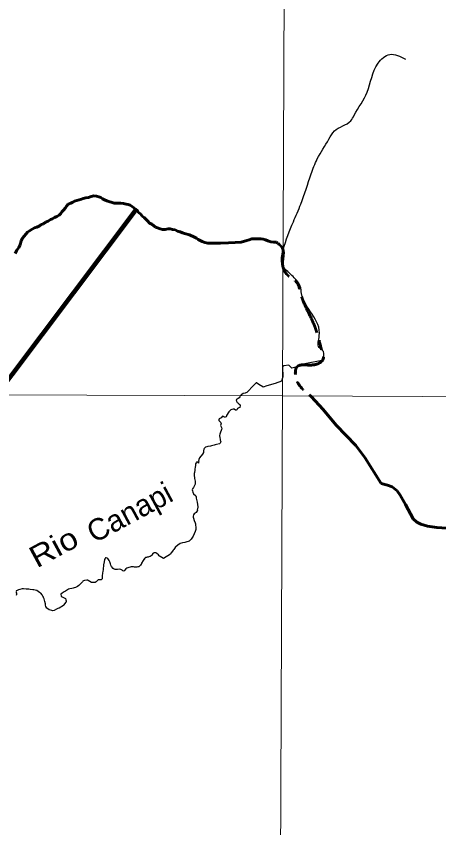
# Model space of a CAD drawing. Extents: x 553962 to 842807, y 8883888 to 9032388.
# Drawn here: x 658730 to 668504, y 8994810 to 9013599 of the extents above; entities that cross this region are included whole.
import ezdxf
from ezdxf.enums import TextEntityAlignment as Align

# ---------------------------------------------------------------- set-up
doc = ezdxf.new("R2010")
doc.units = 0
doc.header["$LTSCALE"] = 150
doc.linetypes.add('LONG_DASH_SHORT_DASH', pattern=[9.9, 6, -1.2, 1.5, -1.2])
for name, color, linetype, lineweight in [('1', 7, 'Continuous', 13), ('24', 7, 'Continuous', 25), ('7', 7, 'LONG_DASH_SHORT_DASH', 60), ('9', 7, 'Continuous', 90)]:
    doc.layers.add(name, color=color, linetype=linetype, lineweight=lineweight)
doc.layers.add('49', color=7, linetype='Continuous')

msp = doc.modelspace()

# ---------------------------------------------------------------- linework, layer by layer
at = {"layer": '1'}
for points in [[(664968.2, 9023436.8), (664657.1, 8949509), (664397.1, 8890880.2)], [(565303.2, 9005146.6), (664889.8, 9004806.7), (719872.1, 9004543.9), (790635.8, 9004109)]]:
    msp.add_lwpolyline(points, dxfattribs=at)
at = {"layer": '24'}
for points in [[(664888.7, 9005478.8), (664900.1, 9005251.2), (664869.8, 9005153.3), (664865.4, 9005145.8), (664717.4, 9005095.4), (664528.5, 9005045), (664441.2, 9005012.7), (664432.8, 9005015.5), (664343.5, 9005072.6), (664286.2, 9005107.2), (664280.8, 9005109), (664271.5, 9005101.5), (664208.7, 9005038.3), (664080.1, 9004905.7)], [(665798.1, 9005626.6), (665405.1, 9005550.8), (665165.6, 9005466.5), (665101.5, 9005450.6), (665032.2, 9005519.9), (664921.3, 9005506.1), (664888.7, 9005478.8)], [(664080.1, 9004905.7), (664063.5, 9004888.7), (664040.8, 9004876.6), (664021.9, 9004870), (663980.2, 9004861.2), (663946.3, 9004843.8), (663931.6, 9004832.2), (663929.7, 9004827.5), (663925.3, 9004825.6), (663922.8, 9004820.1), (663917.9, 9004815.5), (663910.5, 9004801.1), (663899, 9004783.8), (663883.9, 9004765), (663863.8, 9004751.9), (663845.5, 9004742.3), (663830.7, 9004729.4), (663824.8, 9004721.3), (663819.7, 9004702.6), (663823.3, 9004691.5), (663824.1, 9004683.3), (663832.8, 9004668.7), (663842.4, 9004656.8), (663854.1, 9004648.1), (663869.6, 9004633.8), (663887.6, 9004620.7), (663907, 9004598.9), (663907, 9004598.9), (663910.9, 9004584.5), (663902.4, 9004543.4), (663900.7, 9004539.3), (663881.2, 9004529), (663848.8, 9004520.2), (663839.5, 9004493.6), (663833.8, 9004483.1), (663820.7, 9004477), (663803.2, 9004478.8), (663774.4, 9004497.4), (663769.2, 9004499), (663746.7, 9004499.8), (663720.6, 9004496.7), (663695.8, 9004484.7), (663668.4, 9004461.3), (663648.1, 9004440.9), (663597.4, 9004352.2)], [(663597.4, 9004352.2), (663591.9, 9004338.7), (663585.2, 9004327.5), (663562, 9004318.3), (663545.8, 9004318.1), (663534.7, 9004324.6), (663525, 9004333.9), (663497.8, 9004335.9), (663473.3, 9004304.2), (663451.5, 9004291.8), (663425.3, 9004274.1), (663419.2, 9004251.7), (663419.6, 9004240.3), (663428.8, 9004227), (663461.2, 9004195.3), (663463.7, 9004190.3), (663466.9, 9004175.9), (663457.9, 9004121.1), (663483.9, 9004058.1), (663479.5, 9004030.4), (663444.7, 9003947.7), (663436.1, 9003919.8), (663430, 9003892.9), (663436.2, 9003836.4), (663444.6, 9003808.5), (663450.1, 9003780.8), (663459.3, 9003752.9), (663454.4, 9003726), (663450.1, 9003716.1), (663431.3, 9003702.2), (663360.9, 9003681.5), (663332.3, 9003676.8), (663305.3, 9003670.6), (663276.6, 9003659.9), (663248.8, 9003653.3), (663221, 9003644.9), (663165.3, 9003637.2), (663137.5, 9003629.7), (663109.8, 9003617.9), (663077.1, 9003593.6), (663073.8, 9003588.8), (663066.6, 9003572.2), (663061.7, 9003539.8), (663061.5, 9003511.9), (663059.4, 9003496.8), (663040.9, 9003457.1), (662971.2, 9003371.5), (662951.9, 9003338.4), (662948.3, 9003299.8), (662954, 9003282), (662947.1, 9003264.8), (662944, 9003251.6), (662942.9, 9003251.1), (662911.9, 9003278.6), (662899.6, 9003277.8), (662888.3, 9003260.5), (662879.6, 9003232.8), (662873.2, 9003204.9), (662866.8, 9003150.2), (662861.5, 9003121.4), (662858.9, 9003091.8), (662849.7, 9003038), (662846.5, 9003010.2), (662846.6, 9002979.2), (662855.1, 9002895.8), (662859.3, 9002866.8), (662868.7, 9002836.8), (662871.9, 9002808.7), (662871, 9002777.8), (662869.2, 9002761.2), (662849.1, 9002718.3), (662831.4, 9002691.2), (662805.1, 9002656.3), (662801.6, 9002634.7), (662804.8, 9002607.8), (662812, 9002578.7), (662832, 9002539.4), (662877.8, 9002502.9), (662881.5, 9002497.6), (662889.1, 9002470.7), (662893.7, 9002439.9), (662905.9, 9002382.7), (662915.2, 9002349), (662932.3, 9002238.2)], [(662932.3, 9002238.2), (662930.4, 9002232.8), (662918.7, 9002162.2), (662919.1, 9002158.4), (662924.3, 9002149.5), (662924.7, 9002146.9), (662910.5, 9002130.5), (662890.5, 9002112.2), (662844.9, 9002076.1), (662830.6, 9002055.4), (662824.1, 9002025.5), (662826.1, 9001999.9), (662830.2, 9001975), (662842.8, 9001924.6), (662865.6, 9001868.5), (662873.1, 9001845.7), (662878.6, 9001819.2), (662886, 9001766.9), (662885.8, 9001743), (662880.8, 9001718.2), (662866.3, 9001665.2), (662823, 9001561.5), (662795.5, 9001511.2), (662776.8, 9001488.3), (662751.1, 9001464.8), (662727, 9001447.9), (662703, 9001435.9), (662679.1, 9001427.9), (662625.9, 9001415.6), (662573.7, 9001409.9), (662524, 9001394.2), (662471, 9001354.5)], [(662471, 9001354.5), (662418, 9001314.7), (662413.9, 9001313.1), (662387.4, 9001275.2), (662375.4, 9001250.8), (662363.1, 9001233.2), (662344.9, 9001211.6), (662312, 9001177.4), (662303.6, 9001164.2), (662297.6, 9001142.3), (662132.9, 9001044.6), (662055.9, 9001090.7), (662051.5, 9001092.1), (662048.6, 9001095.2), (662046.8, 9001099.7), (662037.3, 9001108.4), (662022.2, 9001125.4), (661983.8, 9001159.7), (661966.6, 9001172.4), (661944.8, 9001178.8), (661926.5, 9001177.5), (661909.8, 9001173.8), (661901.4, 9001170.2), (661890.7, 9001159.3), (661864.8, 9001124.2), (661848.9, 9001108.4), (661829.4, 9001092.8), (661799.7, 9001079.5), (661781.2, 9001073.3), (661761.2, 9001070.8), (661742.7, 9001066.8), (661725.3, 9001066.6), (661721.3, 9001065.5), (661706.2, 9001054.2), (661685.2, 9001030.2), (661683.4, 9001024.9), (661678.4, 9001021.4), (661666.2, 9000995.9)], [(661666.2, 9000995.9), (661666, 9000995.8), (661628.2, 9000939.1), (661629.1, 9000923.3), (661621.8, 9000911.6), (661602.7, 9000889), (661580.6, 9000865.8), (661565.2, 9000853.8), (661545, 9000847.3), (661519.3, 9000842.1), (661468.8, 9000846.1), (661442.2, 9000850.3), (661414.8, 9000850.2), (661390.9, 9000847.2), (661313.8, 9000829), (661288.2, 9000820.3), (661264.1, 9000805.4), (661227.5, 9000755.1), (661208, 9000751.3), (661198.2, 9000757.5), (661179.9, 9000776.4), (661150.3, 9000789.5), (661123.7, 9000793.6), (661075.9, 9000790.6), (661048.4, 9000786.4), (661015, 9000789.2), (660997, 9000798), (660969.6, 9000815.2), (660936.1, 9000861.2), (660916.9, 9000893.2), (660906.5, 9000918), (660902.7, 9000944.6), (660893.5, 9000969.5), (660880.3, 9000995.9), (660864.7, 9001020.9), (660846.7, 9001041.3), (660832.8, 9001051.1), (660807.4, 9001057.7), (660797.2, 9001057), (660783.2, 9001044), (660772.5, 9001021.6), (660765.5, 9000968.5), (660747.9, 9000894.1), (660744.4, 9000865.7), (660743.2, 9000816.2), (660736.9, 9000789.6), (660730.5, 9000739.1), (660724.1, 9000712.6), (660715.8, 9000638.2), (660717.6, 9000586.8), (660716.8, 9000576.4), (660703.4, 9000556.3), (660691.2, 9000550.9), (660651.6, 9000550.6), (660627.7, 9000547.6), (660617, 9000544), (660613.3, 9000541.4), (660580.1, 9000504.8), (660556, 9000490), (660529.6, 9000484.5), (660503.9, 9000484.7), (660470.1, 9000491.9), (660394.1, 9000535.8), (660385, 9000538.7), (660360.5, 9000540.9), (660309.2, 9000533.2), (660284.4, 9000522.9), (660273.5, 9000516.3)], [(660273.5, 9000516.3), (660260.7, 9000503.6), (660242.4, 9000482.3), (660221.6, 9000464.5), (660179.6, 9000416.4), (660146.5, 9000396.3), (660098.7, 9000374.4), (660070.2, 9000365.5), (660046.2, 9000355.7), (660017.1, 9000352.3), (659968.3, 9000340.1), (659941.1, 9000330.8), (659916.1, 9000316.3), (659891.5, 9000299.3), (659868.5, 9000285.3), (659840.5, 9000274.1), (659791.5, 9000243.5), (659791.5, 9000243.5), (659764.1, 9000216.7)], [(658723.2, 9000264.3), (658735.2, 9000237.8), (658736.5, 9000212.6), (658728.3, 9000183.5)], [(659764.1, 9000216.7), (659766.6, 9000170.3), (659768.2, 9000165.1), (659774.5, 9000160.6), (659826.5, 9000142.5), (659840.8, 9000136.1), (659866.7, 9000114.8), (659877.4, 9000088.4), (659881.6, 9000062.4), (659881.8, 9000044.3), (659878.7, 9000033.4), (659825.5, 8999960), (659819.5, 8999953.8), (659723.2, 8999895.5), (659688.5, 8999887.8), (659659.7, 8999873.4), (659605.7, 8999841.4), (659576.1, 8999832.9), (659549.3, 8999836.2), (659494.5, 8999857.3), (659459.2, 8999876.8), (659440.5, 8999897.3), (659416.9, 8999934), (659408.9, 8999962.1), (659405.4, 8999993), (659391.8, 9000051.2), (659380, 9000082), (659373.4, 9000111.9), (659363.4, 9000140), (659357.1, 9000148.2), (659344.6, 9000173.6), (659327.4, 9000201.8), (659297.2, 9000242.3), (659268.6, 9000258.6), (659204.1, 9000299.8), (659165.9, 9000310.6), (659139.1, 9000316.3), (659110, 9000320.5), (659049.2, 9000326.1), (659018.4, 9000330.3), (658960.2, 9000334.5), (658898.5, 9000340.9), (658868.6, 9000338.6), (658809.5, 9000327), (658781.4, 9000320), (658750.4, 9000304), (658731.6, 9000292.7), (658725, 9000283.2)]]:
    msp.add_lwpolyline(points, dxfattribs=at)
msp.add_spline([(665804.3, 9005643.1), (665835.9, 9005832.9), (665741, 9005927.8), (665741, 9006196.7), (665330, 9007177.5), (665298.4, 9007351.5), (665219.3, 9007478.1), (664982.2, 9007715.4), (664887.3, 9007841.9), (664903.2, 9008190), (665140.3, 9008838.5), (665314.2, 9009249.8), (665551.3, 9009945.9), (665693.6, 9010293.9), (665962.4, 9010752.7), (666088.8, 9010942.5), (666468.3, 9011179.8), (666547.3, 9011306.3), (666847.7, 9011844.2), (667100.6, 9012508.6), (667369.4, 9012714.2), (667733, 9012603.5)], degree=3, dxfattribs=at)
at = {"layer": '7'}
for points in [[(659209.3, 9008717), (659256.9, 9008739.8), (659309.5, 9008775.2), (659357.1, 9008795.4), (659404.7, 9008830.8), (659464.8, 9008856.2), (659519.9, 9008891.6), (659567.5, 9008909.3), (659615.1, 9008942.2), (659667.8, 9008962.5), (659725.4, 9008992.9), (659757.9, 9009030.7), (659787.8, 9009070.9), (659822.9, 9009106.2), (659865.3, 9009159.1), (659892.8, 9009199.4), (659930.3, 9009247.3), (659990.4, 9009270.1), (660038.1, 9009290.4), (660080.7, 9009313.2), (660236.1, 9009361.6), (660281.2, 9009379.3), (660341.4, 9009397.2), (660401.7, 9009402.5), (660459.3, 9009422.8), (660527.1, 9009438.2), (660589.8, 9009435.9), (660637.6, 9009421.1), (660685.4, 9009403.7), (660723.1, 9009373.8), (660773.5, 9009346.4), (660826.2, 9009326.5), (660997.2, 9009272.1), (661049.9, 9009272.3), (661152.8, 9009267.7), (661210.6, 9009263), (661270.9, 9009248.2), (661318.6, 9009243.4), (661363.9, 9009226), (661409.2, 9009193.6), (661452, 9009166.2), (661492.3, 9009133.7), (661532.6, 9009096.2), (661560.4, 9009051.2), (661608.2, 9009013.8), (661641.1, 9008966.2), (661691.4, 9008936.3), (661729.2, 9008903.9), (661774.6, 9008851.3), (661814.9, 9008811.4), (661867.8, 9008781.5), (661950.8, 9008716.6), (661998.6, 9008701.8), (662059, 9008674.4), (662116.8, 9008659.6), (662177, 9008659.9), (662242.2, 9008680.2), (662289.9, 9008675.4), (662347.7, 9008658.1), (662403, 9008653.3), (662458.3, 9008623.5), (662518.6, 9008606.2), (662574, 9008583.8), (662624.2, 9008566.5), (662734.8, 9008536.9), (662850.5, 9008479.7), (662898.3, 9008462.3), (662936.1, 9008432.3), (663034.2, 9008380.1), (663089.5, 9008362.8), (663162.3, 9008348), (663225.1, 9008343.3), (663290.4, 9008341.1), (663458.6, 9008341.8), (663636.8, 9008352.6), (663792.4, 9008358.3), (663932.9, 9008369), (664063.3, 9008404.7), (664121, 9008425.1), (664178.6, 9008442.9), (664231.3, 9008448.1), (664334.2, 9008448.6), (664384.5, 9008446.3), (664439.7, 9008439), (664492.5, 9008419.2), (664552.8, 9008401.9), (664615.7, 9008374.6), (664683.5, 9008364.8), (664748.7, 9008365.1)], [(658702, 9008104.8), (658744.3, 9008180.3), (658786.8, 9008240.7), (658809.2, 9008288.5), (658826.6, 9008333.8), (658841.4, 9008396.6), (658876.3, 9008457), (658911.3, 9008504.8), (658993.8, 9008600.6), (659038.9, 9008628.4), (659096.5, 9008668.8), (659149.1, 9008696.6), (659209.3, 9008717)], [(665554.2, 9004795.8), (665826.3, 9004496), (666128.4, 9004129.5), (666582.2, 9003656.2), (666791.2, 9003384.4), (667173.5, 9002782.6), (667316.8, 9002742.9), (667422.9, 9002700.1), (667541.5, 9002608.8), (667614.9, 9002511.4), (667732.4, 9002291), (667913.5, 9001963.7), (667993.5, 9001885.6), (668093.1, 9001836.3), (668244.3, 9001789.9), (668460.2, 9001759), (669127.8, 9001717.8)]]:
    msp.add_lwpolyline(points, dxfattribs=at)
msp.add_spline([(664746.7, 9008367.1), (664889.8, 9008223.9), (664889.8, 9007865.9), (665018.7, 9007593.8), (665247.7, 9007393.2), (665290.6, 9007250), (665362.2, 9007020.9), (665634.2, 9006419.4), (665748.7, 9006047), (665806, 9005832.2), (665834.6, 9005674.7), (665634.2, 9005531.4), (665219.1, 9005474.2), (665190.4, 9005273.6), (665554.2, 9004795.8)], degree=3, dxfattribs=at)
at = {"layer": '9'}
msp.add_lwpolyline([(635350.7, 8977923.9), (636116.8, 8981777.4), (642228, 8989744.8), (647160.3, 8990514), (649828, 8995545.6), (655722.5, 9001435.5), (661506.7, 9009120.3)], dxfattribs=at)

# ---------------------------------------------------------------- texts
at = {"layer": '49'}
msp.add_text('Canapi', height=500, rotation=28.393, dxfattribs=at).set_placement((661469, 9001892.9), align=Align.CENTER)
at = {"layer": '49', "width": 1.15}
msp.add_text('Rio', height=500, rotation=28.393, dxfattribs=at).set_placement((659714, 9001085.8), align=Align.CENTER)

doc.saveas('drawing.dxf')
